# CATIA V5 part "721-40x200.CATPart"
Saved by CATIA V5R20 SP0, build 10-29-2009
Part number: 721-40x200
Definition: NONE
Nomenclature: 721-40x200
Source: Unknown
Description: 721-40x200
Bounding box of the stored display mesh (mm): x -90 to 110, y -35 to 35, z -35 to 35
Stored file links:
  C:\Users\Utente\Desktop\IO LAVORO\3D X SITO CF\X SITO\721\721-40x200.CATPart

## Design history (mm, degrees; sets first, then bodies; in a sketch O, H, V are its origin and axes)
Body1 "721-40x200" (main body)
  Solid1: solid without history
